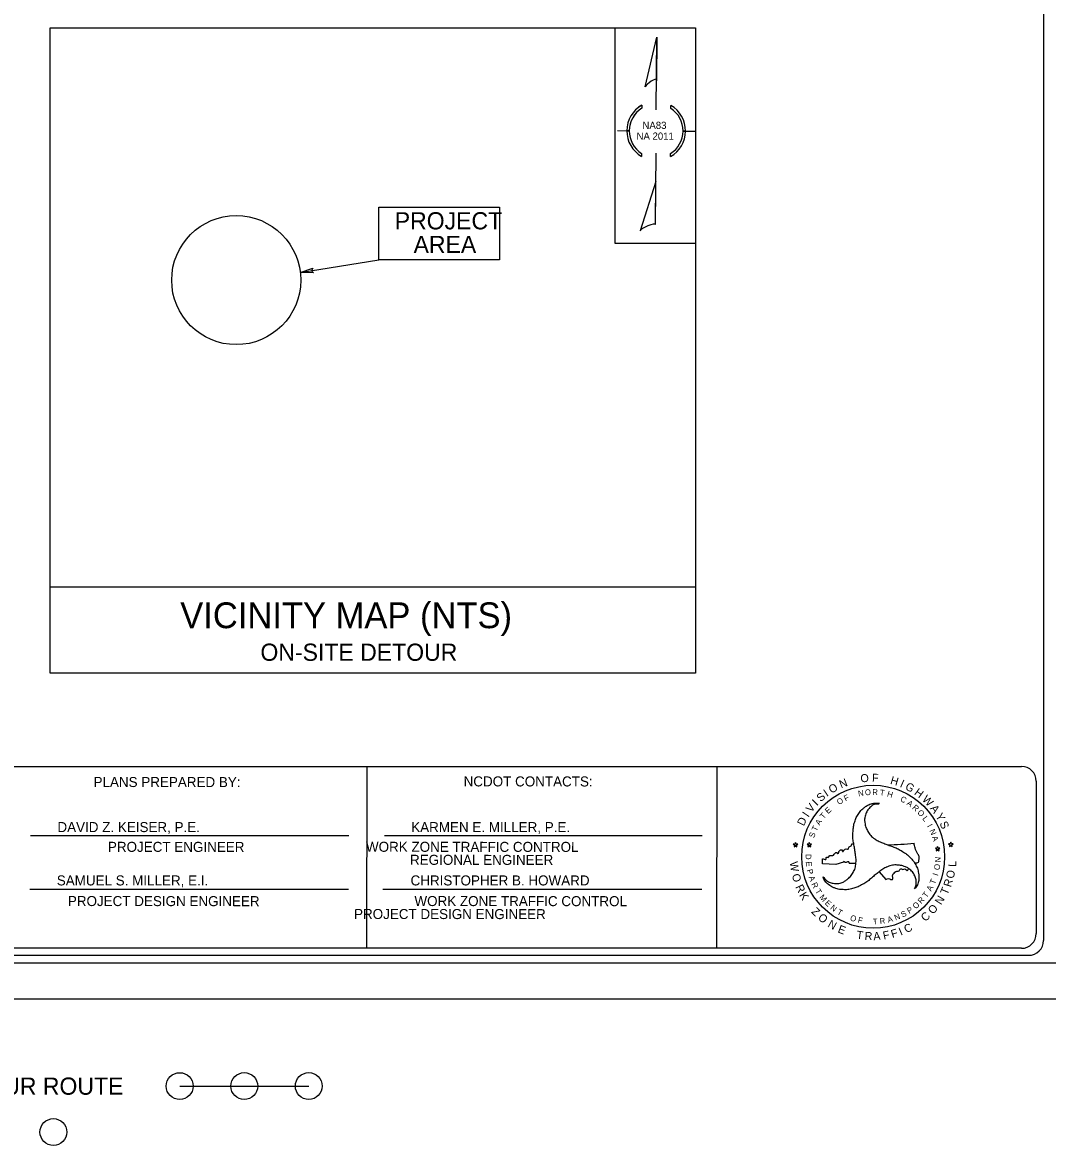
# Model space of a CAD drawing. Extents: x 78728 to 80694, y 10462 to 11664.
# Drawn here: x 79164 to 79879, y 10462 to 11245 of the extents above; entities that cross this region are included whole.
import ezdxf

# ---------------------------------------------------------------- set-up
doc = ezdxf.new("R2010")
doc.units = 0
for name, color, linetype in [('Default', 7, 'Continuous'), ('DEV DOT SWIRL SEAL CELL', 7, 'Continuous'), ('Exist Utilities Gas Test Hole SUE LOS A CELL', 7, 'Continuous'), ('Exist Utilities Sanitary Sewer Test Hole SUE LOS A CELL', 7, 'Continuous'), ('Exist Utilities TV Test Hole SUE LOS A CELL', 7, 'Continuous'), ('Exist Utilities Water Test Hole SUE LOS A CELL', 7, 'Continuous'), ('Sheet Plot Border Outside CELL', 7, 'Continuous'), ('Sheet_Plan_CELL', 7, 'Continuous'), ('Sheet_RDY_XS_Project_Number', 7, 'Continuous')]:
    doc.layers.add(name, color=color, linetype=linetype)

msp = doc.modelspace()

# ---------------------------------------------------------------- linework, layer by layer
at = {"layer": 'Default'}
for p, q in [((79357.75, 11070.43), (79412.44, 11079.38)), ((79404.05, 10726.13), (79403.97, 10599.33)), ((79169.63, 10678.03), (79391.52, 10678)), ((79416.45, 10678.01), (79637.9, 10678)), ((79169.09, 10640.56), (79391.37, 10640.55)), ((79415.41, 10640.58), (79637.71, 10640.54))]:
    msp.add_line(p, q, dxfattribs=at)
msp.add_circle((79313.06, 11065.19), 45, dxfattribs=at)
at = {"layer": 'DEV DOT SWIRL SEAL CELL'}
for p, q in [((79598.17, 11199.88), (79606.27, 11234.6)), ((79605.98, 11183.93), (79606.31, 11234.6)), ((79606.31, 11234.6), (79606.11, 11204.12)), ((79606.31, 11234.6), (79606.27, 11234.6)), ((79606.31, 11234.6), (79606.27, 11234.6)), ((79606.11, 11204.12), (79606.11, 11204.99)), ((79606.11, 11204.99), (79606.13, 11204.98)), ((79595.92, 11187.17), (79595.91, 11185.12)), ((79595.92, 11187.19), (79595.92, 11187.17)), ((79616.09, 11184.98), (79616.1, 11187.02)), ((79578.88, 11169.42), (79587.13, 11169.37)), ((79587.13, 11169.37), (79585.38, 11169.38)), ((79585.38, 11169.38), (79587.13, 11169.37)), ((79624.63, 11169.13), (79632.88, 11169.07)), ((79624.63, 11169.13), (79626.38, 11169.11)), ((79626.38, 11169.11), (79624.63, 11169.13)), ((79595.71, 11153.5), (79595.69, 11151.46)), ((79605.46, 11103.9), (79605.78, 11153.82)), ((79615.87, 11151.34), (79615.88, 11153.39)), ((79615.87, 11151.32), (79615.87, 11151.34)), ((79605.63, 11133.89), (79594.66, 11099.5)), ((79605.47, 11103.9), (79605.63, 11133.89))]:
    msp.add_line(p, q, dxfattribs=at)
for radius, start, end in [(20.5, 119.06355, 240.19523), (18.75, 122.13255, 237.12622), (20.5, 299.14981, 60.10897), (18.75, 302.22997, 57.02881), (18.75, 359.62939, 57.02881), (20.5, 359.62939, 60.10897), (20.5, 179.62939, 240.19523), (18.75, 179.62939, 237.12622)]:
    msp.add_arc((79605.88, 11169.25), radius, start, end, dxfattribs=at)
for centre, major_axis, ratio, start_param, end_param in [((79602.08, 11202.01), (4.01, 3.03), 0.261723, 6.225794, 8.917625), ((79605.88, 11169.25), (0.13, 20.53), 0.998737, 0.514018, 1.570796), ((79605.88, 11169.25), (0.12, 18.77), 0.998737, 0.567287, 1.570796), ((79605.88, 11169.25), (0.13, 20.53), 0.998737, 3.657116, 4.712389), ((79605.88, 11169.25), (0.12, 18.77), 0.998737, 3.71058, 4.712389), ((79600.06, 11101.51), (5.4, 2.39), 0.225493, 6.280036, 9.220301)]:
    msp.add_ellipse(centre, major_axis=major_axis, ratio=ratio, start_param=start_param, end_param=end_param, dxfattribs=at)
at = {"layer": 'Exist Utilities Gas Test Hole SUE LOS A CELL'}
for p, q in [((79875.96, 11623.79), (79875.97, 10604.69)), ((78911.45, 10726.08), (79860.64, 10726.08)), ((79648.13, 10726.16), (79648.04, 10599.37)), ((79870.92, 10715.79), (79870.92, 10609.57)), ((79701.49, 10671.93), (79702.46, 10671.22)), ((79702.69, 10671.93), (79701.49, 10671.93)), ((79702.46, 10671.22), (79702.11, 10670.06)), ((79702.11, 10670.06), (79703.04, 10670.77)), ((79703.04, 10673.04), (79702.69, 10671.93)), ((79703.44, 10671.93), (79703.04, 10673.04)), ((79703.04, 10670.77), (79704.03, 10670.06)), ((79703.04, 10670.77), (79704.02, 10670.06)), ((79704.64, 10671.93), (79703.44, 10671.93)), ((79703.67, 10671.22), (79704.65, 10671.93)), ((79703.67, 10671.22), (79704.64, 10671.93)), ((79704.03, 10670.06), (79703.67, 10671.22)), ((79704.02, 10670.06), (79703.67, 10671.22)), ((79712.3, 10671.92), (79711.1, 10671.92)), ((79711.1, 10671.92), (79712.08, 10671.2)), ((79712.08, 10671.2), (79711.73, 10670.05)), ((79711.73, 10670.05), (79712.66, 10670.76)), ((79712.66, 10673.03), (79712.3, 10671.92)), ((79713.06, 10671.92), (79712.66, 10673.03)), ((79712.66, 10670.76), (79713.64, 10670.05)), ((79714.26, 10671.92), (79713.06, 10671.92)), ((79713.28, 10671.2), (79714.26, 10671.92)), ((79713.64, 10670.05), (79713.28, 10671.2)), ((79801.8, 10669.16), (79800.6, 10669.16)), ((79800.6, 10669.16), (79801.58, 10668.45)), ((79801.58, 10668.45), (79801.22, 10667.29)), ((79801.22, 10667.29), (79802.16, 10668)), ((79802.16, 10670.27), (79801.8, 10669.16)), ((79802.56, 10669.16), (79802.16, 10670.27)), ((79802.16, 10668), (79803.14, 10667.29)), ((79803.76, 10669.16), (79802.56, 10669.16)), ((79802.78, 10668.45), (79803.76, 10669.16)), ((79803.14, 10667.29), (79802.78, 10668.45)), ((79810.97, 10672.09), (79809.77, 10672.09)), ((79809.77, 10672.09), (79810.75, 10671.38)), ((79810.75, 10671.38), (79810.39, 10670.22)), ((79810.39, 10670.22), (79811.33, 10670.93)), ((79811.33, 10673.2), (79810.97, 10672.09)), ((79811.73, 10672.09), (79811.33, 10673.2)), ((79811.33, 10670.93), (79812.31, 10670.22)), ((79812.93, 10672.09), (79811.73, 10672.09)), ((79811.95, 10671.38), (79812.93, 10672.09)), ((79812.31, 10670.22), (79811.95, 10671.38)), ((79721.79, 10658.14), (79721.89, 10661.08)), ((79736.42, 10659.36), (79731.09, 10657.8)), ((79740.52, 10658.74), (79745.19, 10658.7)), ((79731.09, 10657.8), (79721.79, 10658.14)), ((79761.29, 10652.51), (79766.07, 10647.34)), ((79860.64, 10599.33), (78911.46, 10599.33)), ((78901.09, 10589.11), (80380.52, 10589.11)), ((78905.92, 10594.41), (79865.68, 10594.41))]:
    msp.add_line(p, q, dxfattribs=at)
msp.add_circle((79757.19, 10663.11), 49.83, dxfattribs=at)
for centre, radius, start, end in [((79860.64, 10715.79), 10.29, 0.00003, 90.00003), ((79761.72, 10929.82), 258.4, 265.67849, 265.97623), ((79761.72, 10929.82), 258.4, 271.20351, 275.32356), ((79860.64, 10609.57), 10.29, 270.00003, 0.00003), ((79865.68, 10604.69), 10.29, 270.00003, 0.00003)]:
    msp.add_arc(centre, radius, start, end, dxfattribs=at)
for points in [[(79722.25, 10649.15), (79724.18, 10646.92), (79726.59, 10645.38), (79729.36, 10644.66), (79732.48, 10644.48), (79735.67, 10645.23), (79737.78, 10646.3), (79738.67, 10647.01), (79740.22, 10648.23), (79741.32, 10649.42), (79743.16, 10652.04), (79744.59, 10655.13), (79745.18, 10658.67), (79745.21, 10658.97), (79745.18, 10662.3), (79744.74, 10665.66), (79744.26, 10668.9), (79743.66, 10672.26), (79743.13, 10675.6), (79743.07, 10678.84), (79743.28, 10682.56), (79743.82, 10685.74), (79744.86, 10689.01), (79745.42, 10690.56), (79746.19, 10691.81), (79748.13, 10694.75), (79750.66, 10697.13), (79752.32, 10698.38), (79753.9, 10699.22), (79754.17, 10699.36), (79757.32, 10700.37), (79760.41, 10700.49), (79761.46, 10700.22)], [(79761.54, 10700.32), (79761.46, 10700.22), (79758.6, 10699.69), (79756.01, 10698.35), (79754.02, 10696.33), (79752.32, 10693.74), (79751.37, 10690.59), (79751.22, 10688.24), (79751.43, 10687.11), (79751.7, 10685.15), (79752.14, 10683.6), (79753.54, 10680.71), (79755.47, 10677.92), (79758.27, 10675.63), (79758.51, 10675.45), (79761.36, 10673.81), (79764.55, 10672.5), (79767.58, 10671.31), (79770.77, 10670.15), (79773.92, 10668.9), (79776.77, 10667.36), (79779.9, 10665.33), (79782.36, 10663.28), (79784.69, 10660.76), (79785.76, 10659.47), (79786.44, 10658.17), (79788.05, 10655.04), (79788.82, 10651.65), (79789.09, 10649.57), (79789.03, 10647.79), (79789.03, 10647.49), (79788.28, 10644.25), (79786.83, 10641.51), (79786.11, 10640.77)], [(79721.89, 10661.08), (79721.79, 10661.37), (79722.3, 10661.68), (79723.67, 10661.12), (79724.36, 10661.71), (79724.33, 10662.31), (79724.89, 10662.9), (79725.83, 10662.71), (79726.68, 10663.78), (79727.46, 10664), (79729.12, 10664), (79731.09, 10665.97), (79731.91, 10666.09), (79732.13, 10665.56), (79732.63, 10665.47), (79733.5, 10667.1), (79733.72, 10667.32), (79735.22, 10667.94), (79735.63, 10667.63), (79735.76, 10666.91), (79735.98, 10666.78), (79736.48, 10667.13), (79737.17, 10668.01), (79738.42, 10668.66), (79739.86, 10668.47), (79740.11, 10669.67), (79741.8, 10670.79), (79742.14, 10671.48), (79742.24, 10672.17)], [(79786.03, 10658.99), (79788.77, 10659.33), (79789.17, 10661.49), (79789.2, 10663.31), (79788.08, 10665.41), (79786.39, 10669.26), (79785.7, 10672.55)], [(79740.52, 10658.74), (79740.14, 10659.46), (79739.39, 10659.68), (79738.36, 10659.14), (79737.6, 10659.17), (79736.76, 10659.8), (79736.42, 10659.36)], [(79786.11, 10640.77), (79787.07, 10643.5), (79787.21, 10646.39), (79786.44, 10649.15), (79785.04, 10651.92), (79782.81, 10654.3), (79780.85, 10655.61), (79779.75, 10656), (79777.96, 10656.77), (79776.33, 10657.12), (79773.17, 10657.39), (79769.75, 10657.09), (79766.39, 10655.82), (79766.12, 10655.7), (79763.27, 10654), (79760.56, 10651.95), (79757.97, 10649.93), (79755.39, 10647.72), (79752.74, 10645.58), (79749.97, 10643.92), (79746.64, 10642.22), (79743.64, 10641.12), (79740.31, 10640.38), (79738.64, 10640.08), (79737.18, 10640.14), (79733.7, 10640.32), (79730.34, 10641.33), (79728.44, 10642.13), (79726.92, 10643.11), (79726.65, 10643.26), (79724.21, 10645.49), (79722.58, 10648.11), (79722.25, 10649.15)], [(79766.07, 10647.34), (79767.95, 10647.9), (79769.51, 10647.31), (79770.26, 10647.18), (79770.89, 10647.65), (79770.7, 10650), (79771.23, 10651.1), (79773.77, 10652.98), (79775.34, 10653.32), (79776.49, 10654.76), (79776.96, 10654.73), (79777.68, 10654.32), (79779.28, 10654.64), (79780.56, 10653.6), (79781.31, 10653.66), (79781.92, 10654.84)]]:
    msp.add_spline(points, degree=3, dxfattribs=at)
at = {"layer": 'Exist Utilities Sanitary Sewer Test Hole SUE LOS A CELL'}
msp.add_lwpolyline([(79366.88, 11070.36), (79357.75, 11070.43), (79366.42, 11073.47), (79365.55, 11071.71)], close=True, dxfattribs=at)
at = {"layer": 'Exist Utilities TV Test Hole SUE LOS A CELL'}
msp.add_lwpolyline([(79412.44, 11116.07), (79496.71, 11116.07), (79496.71, 11079.38), (79412.44, 11079.38)], close=True, dxfattribs=at)
at = {"layer": 'Exist Utilities Water Test Hole SUE LOS A CELL'}
msp.add_line((79273.67, 10503.17), (79363.67, 10503.2), dxfattribs=at)
at = {"layer": 'Sheet Plot Border Outside CELL'}
msp.add_lwpolyline([(78727.81, 10564.11), (80415.81, 10564.11), (80415.81, 11664.11), (78727.81, 11664.11)], close=True, dxfattribs=at)
at = {"layer": 'Sheet_Plan_CELL'}
for points in [[(79183.24, 10851.06), (79183.24, 11241.06), (79577.16, 11241.06), (79577.16, 11091.06), (79633.24, 11091.06), (79633.24, 10851.06)], [(79183.24, 11241.06), (79633.24, 11241.06), (79633.24, 10791.06), (79183.24, 10791.06)]]:
    msp.add_lwpolyline(points, close=True, dxfattribs=at)
at = {"layer": 'Sheet_RDY_XS_Project_Number'}
for centre in [(79273.67, 10503.17), (79273.67, 10503.17), (79318.67, 10503.19), (79318.67, 10503.19), (79363.67, 10503.2), (79363.67, 10503.2), (79185.6, 10471.12), (79185.6, 10471.12)]:
    msp.add_circle(centre, 9.38, dxfattribs=at)

# ---------------------------------------------------------------- texts
at = {"layer": 'Default'}
for s, p in [('PLANS PREPARED BY:', (79213.58, 10711.75)), ('NCDOT CONTACTS:', (79471.63, 10712.17)), ('PROJECT ENGINEER', (79223.61, 10666.54)), ('                              WORK ZONE TRAFFIC CONTROL', (79325.52, 10666.63)), ('                                REGIONAL ENGINEER', (79351.04, 10657.55)), ('PROJECT DESIGN ENGINEER', (79195.68, 10628.74)), ('WORK ZONE TRAFFIC CONTROL', (79437.33, 10628.74)), ('                                             PROJECT DESIGN ENGINEER', (79278.2, 10619.79))]:
    msp.add_text(s, height=7, rotation=359.9598, dxfattribs=at).set_placement(p)
for s, p in [('       DAVID Z. KEISER, P.E.       ', (79170.21, 10680.31)), ('       KARMEN E. MILLER, P.E.      ', (79416.89, 10680.3)), ('       SAMUEL S. MILLER, E.I.      ', (79169.75, 10643.11)), ('       CHRISTOPHER B. HOWARD      ', (79416.42, 10643.1))]:
    msp.add_text(s, height=7, dxfattribs=at).set_placement(p)
at = {"layer": 'DEV DOT SWIRL SEAL CELL'}
for s, p in [('NA83', (79596.34, 11170.63)), ('NA 2011', (79592.21, 11163.13))]:
    msp.add_text(s, height=5, dxfattribs=at).set_placement(p)
at = {"layer": 'Exist Utilities Gas Test Hole SUE LOS A CELL'}
for s, height, rotation, p in [('O', 5.58, 5.76495, (79748.61, 10714.89)), ('F', 5.58, 357.25753, (79756.32, 10715.51)), ('O', 5.58, 30.09348, (79728.1, 10707.02)), ('N', 5.58, 21.58606, (79734.87, 10710.76)), ('H', 5.58, 343.45399, (79768.76, 10714.08)), ('I', 5.58, 335.80403, (79775.4, 10712.01)), ('G', 5.58, 331.5167, (79778.99, 10710.47)), ('S', 5.58, 40.58484, (79720.63, 10701.1)), ('I', 5.58, 34.38082, (79724.92, 10704.77)), ('F', 4.02, 24.25691, (79737.86, 10701.7)), ('N', 4.02, 9.02265, (79746.97, 10705.16)), ('O', 4.02, 3.94457, (79751.57, 10705.95)), ('R', 4.02, 358.86648, (79756.53, 10706.26)), ('T', 4.02, 353.7884, (79761.66, 10706.01)), ('H', 4.02, 343.63223, (79766.58, 10705.3)), ('H', 5.58, 323.46323, (79785.36, 10706.87)), ('W', 5.58, 315.81328, (79790.9, 10702.65)), ('V', 5.58, 51.5806, (79714.1, 10693.54)), ('I', 5.58, 44.87218, (79717.91, 10698.3)), ('E', 4.02, 44.56924, (79725.87, 10692.8)), ('O', 4.02, 29.33499, (79733.2, 10699.1)), ('C', 4.02, 333.47606, (79775.71, 10702.07)), ('A', 4.02, 323.31989, (79780.25, 10699.71)), ('R', 4.02, 318.24181, (79784.12, 10696.88)), ('A', 5.58, 306.77624, (79796.64, 10696.78)), ('D', 5.58, 63.45904, (79708.8, 10684.15)), ('I', 5.58, 55.86794, (79711.96, 10690.28)), ('T', 4.02, 49.64733, (79722.71, 10689.13)), ('O', 4.02, 313.16372, (79787.67, 10693.66)), ('L', 4.02, 308.08564, (79791.24, 10689.58)), ('Y', 5.58, 299.74838, (79800.42, 10691.63)), ('T', 4.02, 64.88158, (79717.72, 10680.52)), ('A', 4.02, 59.8035, (79719.87, 10684.72)), ('I', 4.02, 297.92947, (79794.61, 10684.59)), ('N', 4.02, 292.85138, (79796.3, 10681.37)), ('S', 5.58, 293.2249, (79803.35, 10686.47)), ('S', 4.02, 69.95967, (79715.96, 10675.92)), ('A', 4.02, 287.7733, (79798.07, 10676.88)), ('W', 5.58, 278.14998, (79699.03, 10659.38)), ('D', 4.02, 270.27201, (79710.04, 10665)), ('E', 4.02, 275.35009, (79710.17, 10659.61)), ('N', 4.02, 87.73296, (79804.22, 10659.06)), ('L', 5.58, 87.42899, (79815.03, 10655.97)), ('O', 5.58, 287.11471, (79700.33, 10650.36)), ('P', 4.02, 285.50626, (79710.84, 10653.85)), ('I', 4.02, 72.77072, (79802.33, 10649.5)), ('O', 4.02, 82.92689, (79803.52, 10653.66)), ('O', 5.58, 78.98964, (79813.36, 10647.56)), ('R', 5.58, 295.55406, (79702.81, 10642.15)), ('A', 4.02, 290.58434, (79712.17, 10648.91)), ('R', 4.02, 295.66243, (79714.02, 10644.1)), ('T', 4.02, 67.69263, (79800.11, 10643.53)), ('R', 5.58, 72.75186, (79811.33, 10641.55)), ('K', 5.58, 301.79184, (79705.41, 10636.37)), ('T', 4.02, 300.74051, (79716.55, 10639.22)), ('M', 4.02, 310.89668, (79719.45, 10634.68)), ('R', 4.02, 47.38029, (79790.77, 10629.98)), ('T', 4.02, 52.45838, (79794.37, 10634.13)), ('A', 4.02, 62.61455, (79797.65, 10638.71)), ('N', 5.58, 58.89198, (79804.59, 10629.2)), ('T', 5.58, 66.88101, (79808.84, 10636.12)), ('Z', 5.58, 316.16875, (79713.68, 10624.35)), ('E', 4.02, 315.97477, (79723.15, 10630.45)), ('N', 4.02, 321.05285, (79726.94, 10626.95)), ('P', 4.02, 32.14604, (79782.34, 10623.24)), ('O', 4.02, 42.30221, (79786.86, 10626.37)), ('O', 5.58, 50.45263, (79799.1, 10622.61)), ('O', 5.58, 322.52328, (79718.23, 10619.77)), ('N', 5.58, 330.96263, (79725.02, 10614.52)), ('T', 4.02, 331.20902, (79731.64, 10623.36)), ('O', 4.02, 341.36519, (79740.74, 10618.91)), ('F', 4.02, 346.44327, (79746.19, 10617.27)), ('T', 4.02, 1.67753, (79757.01, 10615.94)), ('R', 4.02, 6.75561, (79761.98, 10616.21)), ('A', 4.02, 16.91178, (79767.81, 10617.07)), ('N', 4.02, 21.98987, (79772.88, 10618.6)), ('S', 4.02, 27.06795, (79777.77, 10620.68)), ('C', 5.58, 43.08071, (79793.56, 10617.57)), ('E', 5.58, 338.95166, (79732.08, 10610.52)), ('T', 5.58, 352.69479, (79745.3, 10606.06)), ('F', 5.58, 11.77506, (79764.6, 10605.31)), ('F', 5.58, 17.76266, (79770.59, 10606.4)), ('I', 5.58, 23.75026, (79776.43, 10608.1)), ('C', 5.58, 28.0033, (79780.46, 10609.68)), ('R', 5.58, 358.56564, (79751.19, 10605.14)), ('A', 5.58, 4.80342, (79757.53, 10604.84))]:
    msp.add_text(s, height=height, rotation=rotation, dxfattribs=at).set_placement(p)
at = {"layer": 'Exist Utilities TV Test Hole SUE LOS A CELL'}
for s, p in [('PROJECT ', (79423.6, 11100.57)), ('AREA', (79436.74, 11084.07))]:
    msp.add_text(s, height=12, rotation=360, dxfattribs=at).set_placement(p)
at = {"layer": 'Sheet_Plan_CELL'}
for s, height, p in [('VICINITY MAP (NTS)', 18, (79274.04, 10822.5)), ('ON-SITE DETOUR', 12, (79329.95, 10799.74)), ('DETOUR ROUTE', 12, (79106.03, 10497.17))]:
    msp.add_text(s, height=height, rotation=360, dxfattribs=at).set_placement(p)

doc.saveas('drawing.dxf')
